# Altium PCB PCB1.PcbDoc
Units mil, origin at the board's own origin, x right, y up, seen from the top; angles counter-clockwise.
Board outline 3605 x 1868.38 mil, 2 copper layers (Top Layer, Bottom Layer); 67 components, 41 nets, 188 pads, 47 vias.
Unrouted connection lines stored in the file: 5.
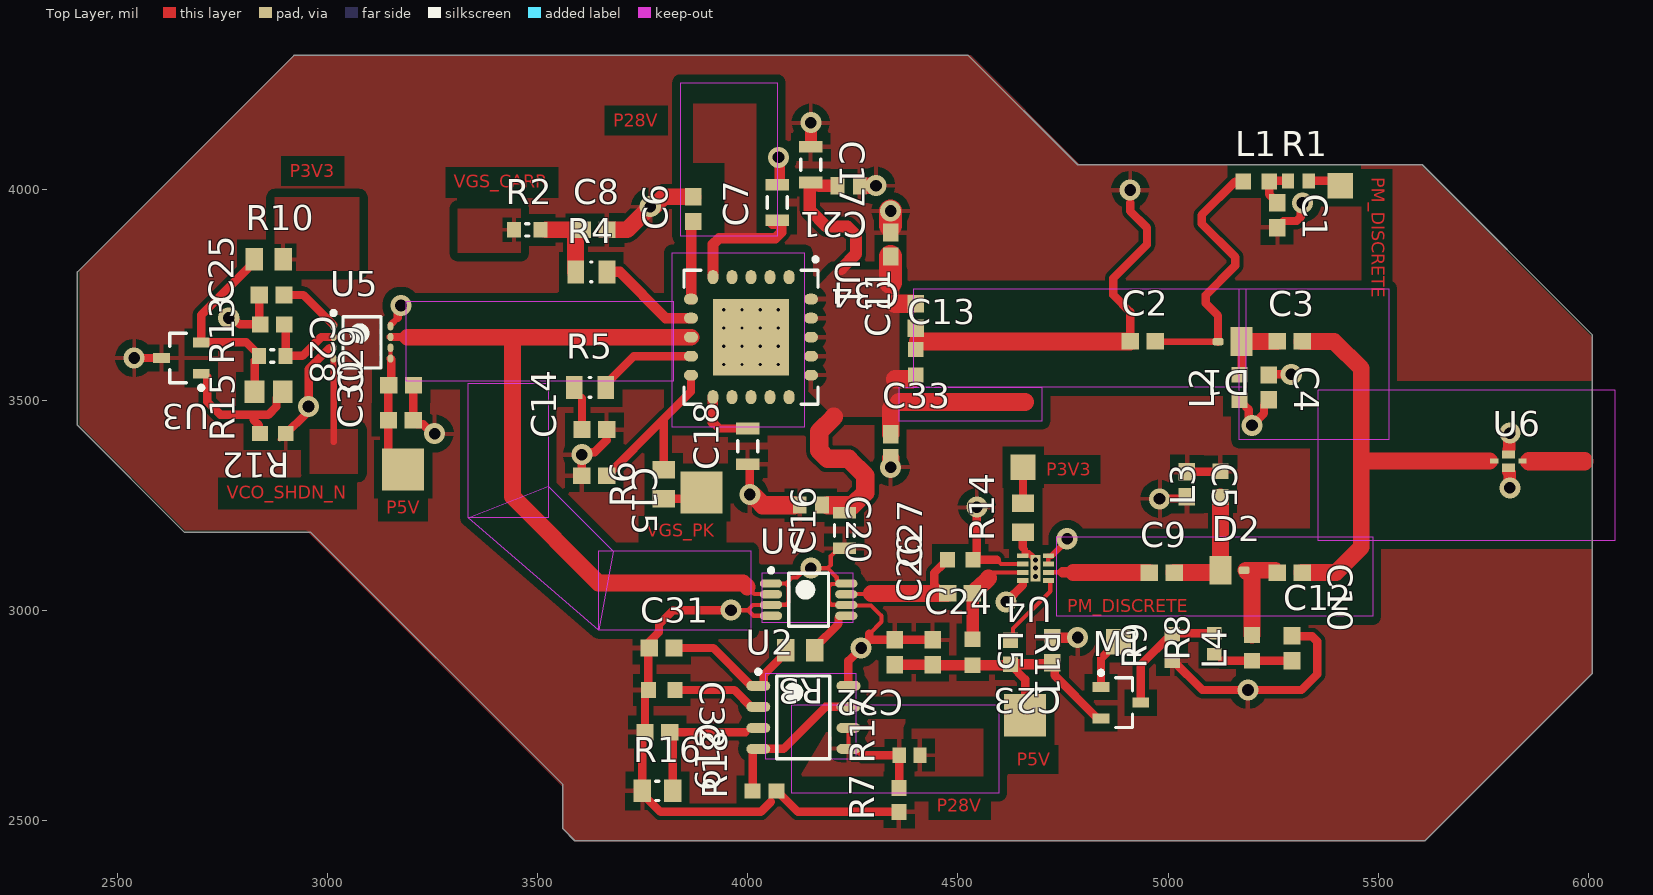
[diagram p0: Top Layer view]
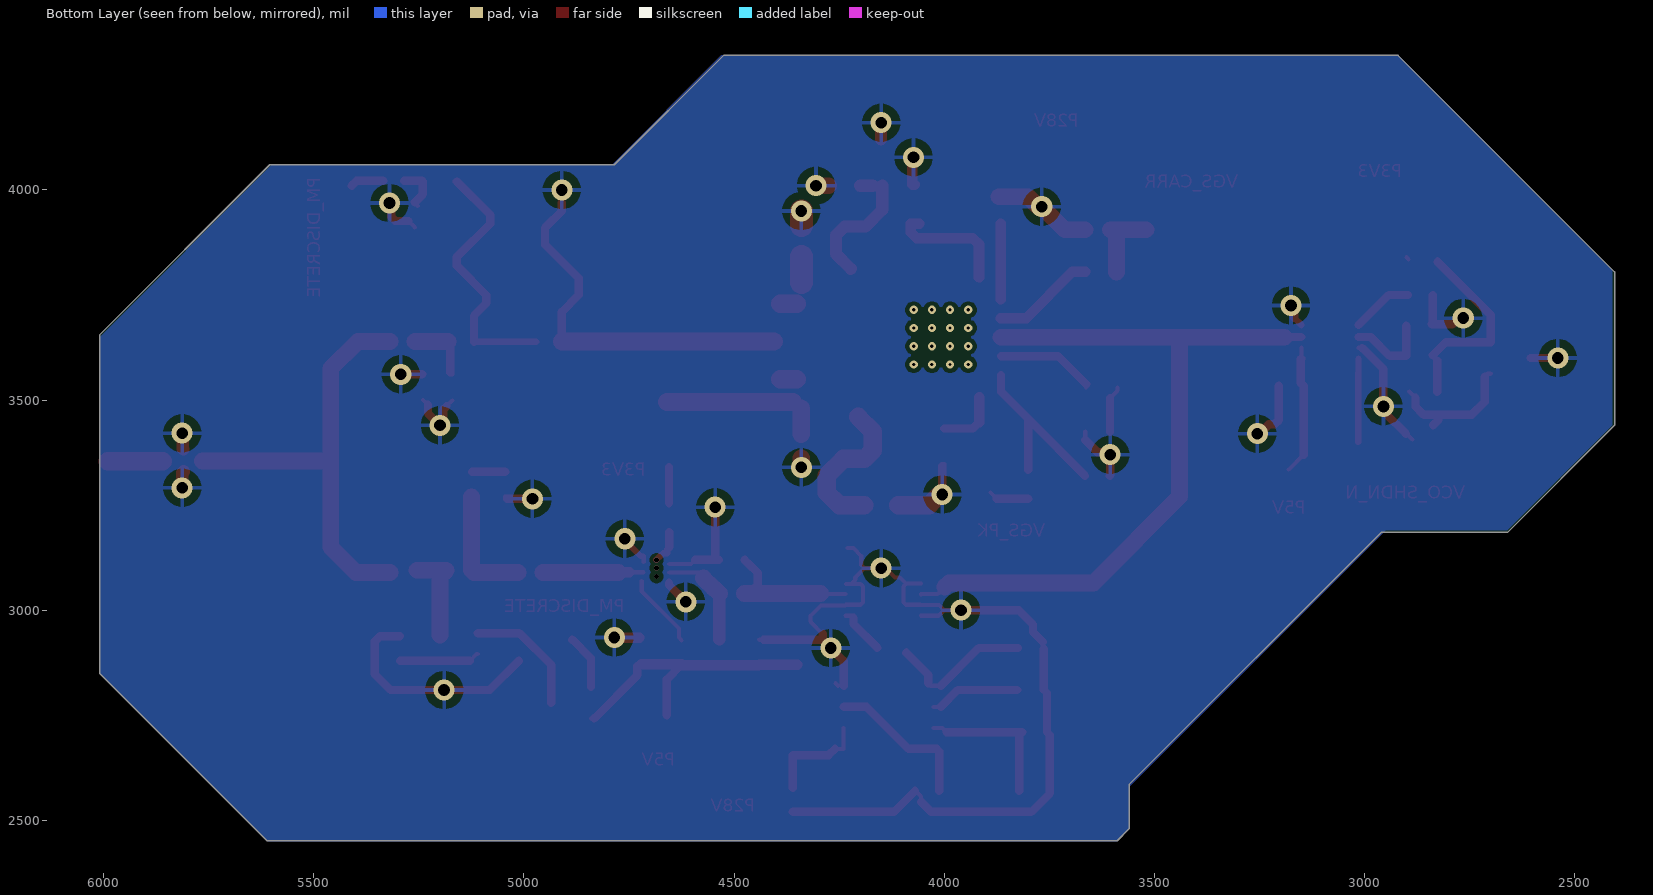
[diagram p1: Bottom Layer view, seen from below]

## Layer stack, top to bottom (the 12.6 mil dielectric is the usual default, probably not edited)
Top Layer: signal copper 1.378
Dielectric 1: dielectric 12.6, FR-4, Dk 4.8
Bottom Layer: signal copper 1.378

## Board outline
2660,3185 2405,3440 2405,3805 2920,4320 4525,4320 4785,4060 5605,4060 6010,3655 6010,2850 5611.62,2451.62 3588.38,2451.62 3560,2480 3560,2585 2960,3185

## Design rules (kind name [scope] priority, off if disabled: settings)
Clearance Clearance_1 [All] p1: gap=10 ignorepadtopadclearanceinfootprint=FALSE except(0: Arc-Hole Track-Hole SMDPad-Hole THPad-Hole Via-Hole Fill-Hole Poly-Hole Region-Hole Text-Hole; 20: Track-Region SMDPad-Poly Fill-Fill Fill-Poly Fill-Region Poly-Poly Poly-Region Region-Region)
PlaneConnect [All] p1: planeconnectstyle=Relief reliefexpansion=20 reliefentries=4 reliefconductorwidth=10 reliefairgap=20
PolygonConnect [All] p1: connectstyle=Relief reliefconductorwidth=10 reliefentries=4 polygonreliefangle="90 Angle" airgapwidth=20
RoomDefinition 33-1-001_R01 [InComponentClass('33-1-001_R01')] p1: confinementstyle=ConfineIn formatcopy=TRUE lockcomponents=FALSE outline 8825,45 14100,45 14100,2135 8825,2135
RoutingVias [All] p1: holewidth=28 width=50 viastyle="Through Hole" minholewidth=28 minwidth=50 maxholewidth=28 maxwidth=50
SolderMaskExpansion [All] p1: expansion=4 istentingtop=FALSE
Width [All] p1: maxlimit=10 minlimit=10 preferedwidth=10
29 further rules are at their usual default settings.

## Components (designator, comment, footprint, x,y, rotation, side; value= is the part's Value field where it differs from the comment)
C1 "C00000013" C0603C101J5GAC7082 5260,3940 r270 top
C2 "C00000013" C0603C101J5GAC7082 4940,3640 r0 top
C3 "C00000013" C0603C101J5GAC7082 5289.53,3639.53 r0 top
C4 "C00000013" C0603C101J5GAC7082 5240,3530 r270 top
C5 "C00000013" C0603C101J5GAC7082 5045,3299.53 r270 top
C6 "C00000007" 06033D105KAT2A 3870,3954.53 r90 top
C7 "C00000003" C2012X5R1V106K125AC 4070,3970 r90 top
C8 "C00000007" 06033D105KAT2A 3635.47,3905 r0 top
C9 "C00000013" C0603C101J5GAC7082 4985,3089.53 r0 top
C10 "C00000013" C0603C101J5GAC7082 5289.53,3089.53 r0 top
C11 "C00000007" 06033D105KAT2A 4400,3700 r90 top
C12 "C00000013" C0603C101J5GAC7082 5295,2909.25 r90 top
C13 "C00000005" CBR06C508A5GAC 4400,3590 r90 top
C14 "C00000007" 06033D105KAT2A 3635,3430 r180 top
C15 "C00000007" 06033D105KAT2A 3634.53,3320 r0 top
C16 "C00000003" C2012X5R1V106K125AC 4230,3190 r90 top
C17 "C00000003" C2012X5R1V106K125AC 4150,4060 r270 top
C18 "C00000003" C2012X5R1V106K125AC 4000,3390 r90 top
C19 "C00000011" C0603C104K4RACTU 3785,2710 r0 top
C20 "C00000004" 06035U9R1BAT2A 4150,3250 r0 top
C21 "C00000004" 06035U9R1BAT2A 4240,4010 r180 top
C22 "C00000007" 06033D105KAT2A 4350,2900 r270 top
C23 "C00000013" C0603C101J5GAC7082 4725,2904.53 r270 top
C24 "C00000013" C0603C101J5GAC7082 4440,2900 r90 top
C25 "C00000011" C0603C104K4RACTU 2866.89,3750 r180 top
C26 "C00000008" GQM1875C2E1R6BB12D 4505,3040 r180 top
C27 "C00000005" CBR06C508A5GAC 4505.51,3120 r180 top
C28 "C00000001" C0603C184J3RACTU 2868.86,3680 r0 top
C29 "C00000012" C0603C221J3RACAUTO 3175,3535 r180 top
C30 "C00000012" C0603C221J3RACAUTO 3174.53,3451.97 r180 top
C31 "C00000007" 06033D105KAT2A 3795,2910 r0 top
C32 "C00000014" AC0603KRX7R8BB103 3795,2810 r0 top
C33 "C00000010" VJ0603D1R8BXCQJHT 4340,3390 r90 top
C34 "C00000010" VJ0603D1R8BXCQJHT 4340,3870 r270 top
D1 "D00000001" SMP1334-084LF 5140,3640 r180 top
D2 "D00000001" SMP1334-084LF 5160,3094 r0 top
L1 "L00000001" ILC0603ER22NJ 5210,4020 r0 top
L2 "L00000001" ILC0603ER22NJ 5170,3530 r90 top
L3 "L00000001" ILC0603ER22NJ 5125,3300 r90 top
L4 "L00000001" ILC0603ER22NJ 5200,2910.24 r90 top
L5 "L00000001" ILC0603ER22NJ 4535,2900 r270 top
M1 "BSS84" BSS84,215 4887.76,2780 r0 top
R1 "R00000009" CR0603-JW-820ELF 5310,4021.57 r0 top
R2 "R00000008" ERJ-U3RD8200V 3475,3905 r0 top
R3 "R00000003" SFR10EZPF10R0 4125,2905 r180 top
R4 "R00000004" CRCW08055R10FKTA 3627.6,3805 r0 top
R5 "R00000004" CRCW08055R10FKTA 3625,3530 r0 top
R6 "R00000003" SFR10EZPF10R0 3800,3300 r90 top
R7 "R00000011" ESR03EZPJ432 4360,2548.54 r90 top
R8 "R00000009" CR0603-JW-820ELF 5110,2920.08 r90 top
R9 "R00000001" ERJ-UP3F8660V 5010,2911.22 r90 top
R10 "R00000005" CR0805-FX-1580ELF 2860.55,3835 r0 top
R11 "R00000011" ESR03EZPJ432 4625,2900 r270 top
R12 "R00000006" ERA-6AEB101V 2860,3520 r180 top
R13 "R00000001" ERJ-UP3F8660V 2868.86,3605 r180 top
R14 "R00000010" CR0805-JW-203ELF 4655,3220 r90 top
R15 "R00000007" "RN73H1JTTD43R7B25 - duplicate" 2870,3420 r180 top
R16 "R00000012" RK73H2ATTD3832F 3785,2570 r0 top
R17 "R00000013" RCS0603499RFKEA 4385,2655 r180 top
R18 "R00000011" ESR03EZPJ432 4040,2570 r180 top
U1 "IC BLM9D2327-26B" BLM9D2327-26B 4007.72,3649.72 r270 top
U2 "IC LM2907" LM2907 4132.28,2745 r0 top
U3 "IC TL4051AQDBZR" TL4051AQDBZR 2652.24,3600 r180 top
U4 "IC QPL9503" QPL9503 4711.57,3117.72 r180 top
U5 "IC MAX 2750 VCO" MAX2750EUA+ 3082.09,3637.2 r0 top
U6 "DEA162495BT-1289A1" DEA162495BT-1289A1 5810,3355 r0 top
U7 "IC HMC213BMS8E" HMC213BMS8E 4145,3025 r0 top

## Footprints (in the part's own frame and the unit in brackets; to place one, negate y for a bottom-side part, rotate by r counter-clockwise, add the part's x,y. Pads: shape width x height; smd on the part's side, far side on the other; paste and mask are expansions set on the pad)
06033D105KAT2A [mm] "Multilayer Ceramic Capacitors MLCC - SMD/SMT 25V 1uF X5R 0603 10%"
  rect 1.05x1 smd: 1(-0.75,0) 2(0.75,0)
  body extent -0.88,-0.48 0.87,0.48, height 0.8
06035U9R1BAT2A [mm] "Multilayer Ceramic Capacitors MLCC - SMD/SMT 50V 9.1pF C0G 0603 0.1pF"
  rect 0.84x1.04 smd: 1(-0.67,0) 2(0.67,0)
  body extent -0.89,-0.51 0.88,0.5, height 0.91
AC0603KRX7R8BB103 [mm] "Multilayer Ceramic Capacitors MLCC - SMD/SMT 25V 0.01uF X7R 0603 10% AEC-Q200"
  rect 0.9x0.95 smd: 1(-0.8,0) 2(0.8,0)
  body extent -0.85,-0.45 0.85,0.45, height 0.55
BLM9D2327-26B [mm] "LDMOS 2-stage integrated Doherty MMIC"
  oval 0.85x0.65 smd: 1(-3.625,2.3) 2(-3.625,1.15) 3(-3.625,0) 4(-3.625,-1.15) 5(-3.625,-2.3) 11(3.625,-2.3) 12(3.625,-1.15) 13(3.625,0) 14(3.625,1.15) 15(3.625,2.3)
  oval 0.65x0.85 smd: 6(-2.3,-3.625) 7(-1.15,-3.625) 8(0,-3.625) 9(1.15,-3.625) 10(2.3,-3.625) 16(2.3,3.625) 17(1.15,3.625) 18(0,3.625) 19(-1.15,3.625) 20(-2.3,3.625)
  rect 4.62x4.62 smd: 21(0,0)
  silkscreen extent -4.82,-4.05 4.05,4.05, body extent -4.05,-4.05 4.05,4.05, height 2.2
BSS84,215 [mm] "MOSFET P-CH DMOS 50V 130MA"
  rect 1x0.6 smd: 1(-1.2,0.95) 2(-1.2,-0.95) 3(1.2,0)
  silkscreen extent -1.32,-1.5 0.7,1.92, body extent -0.7,-1.5 0.7,1.5, height 1.1
C0603C101J5GAC7082 [mm] "MLCC - SMD/SMT 50V 100pF 0603 C0G 0.05"
  rect 1.05x1 smd: 1(-0.75,0) 2(0.75,0)
  body extent -0.88,-0.48 0.87,0.47, height 0.8
C0603C104K4RACTU [mm] "MLCC - SMD/SMT 16V 0.1uF X7R 0603 10%"
  rect 1.05x1 smd: 1(-0.75,0) 2(0.75,0)
  body extent -0.88,-0.48 0.87,0.47, height 0.8
C0603C184J3RACTU [mm] "Multilayer Ceramic Capacitors MLCC - SMD/SMT 25V 0.18uF X7R 0603 5%"
  rect 1x0.95 smd: 1(-0.725,0) 2(0.725,0)
  body extent -0.87,-0.48 0.87,0.48, height 0.8
C0603C221J3RACAUTO [mm] "MLCC - SMD/SMT 25V 220pF X7R 0603 5% AEC-Q200"
  rect 1.05x1 smd: 1(-0.75,0) 2(0.75,0)
  body extent -0.88,-0.48 0.87,0.47, height 0.8
C2012X5R1V106K125AC [mm] "Multilayer Ceramic Capacitors MLCC - SMD/SMT 0805 35V 10uF X5R 10% T: 1.25mm"
  rect 0.7x1.4 smd: 1(-1.075,0) 2(1.075,0)
  silkscreen extent -0.35,-0.6 0.35,0.6, body extent -1,-0.63 1,0.63, height 1.25
CBR06C508A5GAC [mm] "Multilayer Ceramic Capacitors MLCC - SMD/SMT 50V 0.5pF C0G 0603 0.05pF"
  rect 0.9x0.95 smd: 1(-0.775,0) 2(0.775,0)
  body extent -0.85,-0.45 0.85,0.45, height 0.87
CR0603-JW-820ELF [mm] "Thick Film Resistors - SMD 82 OHM 5%"
  rect 0.75x0.9 smd: 1(-0.625,0) 2(0.625,0)
  body extent -0.8,-0.45 0.8,0.45, height 0.8
CR0805-FX-1580ELF [mm] "Thick Film Resistors - SMD 158ohm 1%"
  rect 1.05x1.35 smd: 1(-0.875,0) 2(0.875,0)
  body extent -1.05,-0.67 1.05,0.67, height 0.6
CR0805-JW-203ELF [mm] "Thick Film Resistors - SMD 20K 5%"
  rect 1.05x1.35 smd: 1(-0.875,0) 2(0.875,0)
  body extent -1.05,-0.67 1.05,0.67, height 0.6
CRCW08055R10FKTA [mm] "Thick Film Resistors - SMD 1/8watt 5.1ohms 1%"
  rect 1x1.4 smd: 1(-0.95,0) 2(0.95,0)
  silkscreen extent -0.05,-0.6 0.05,0.6, body extent -1.1,-0.7 1.1,0.7, height 0.5
DEA162495BT-1289A1 [mm] "Multilayer Band Pass Filter  For 2300-2690MHz"
  rect 0.5x0.3 smd: 1(0.85,0) 3(-0.85,0)
  rect 0.8x0.5 smd: 2(0,-0.4) 4(0,0.4)
ERA-6AEB101V [mm] "Thin Film Resistors - SMD 0805 1/8W 100ohms"
  rect 1.2x1.35 smd: 1(-0.85,0) 2(0.85,0)
  body extent -1.1,-0.67 1.1,0.67, height 0.6
ERJ-U3RD8200V [mm] "Thick Film Resistors - SMD 0603 Anti-sulfur"
  rect 0.85x0.95 smd: 1(-0.8,0) 2(0.8,0)
  silkscreen extent -0.1,-0.38 0.1,0.38, body extent -0.88,-0.48 0.87,0.48, height 0.55
ERJ-UP3F8660V [mm] "Thick Film Resistors - SMD 0603 0.25W 1% 866ohm AEC-Q200"
  rect 0.85x0.95 smd: 1(-0.8,0) 2(0.8,0)
  silkscreen extent -0.1,-0.38 0.1,0.38, body extent -0.88,-0.48 0.87,0.48, height 0.55
ESR03EZPJ432 [mm] "Thick FilmResistors - SMD 0603 4.3Kohm 5% Anti Surge AEC-Q200"
  rect 0.95x0.9 smd: 1(-0.725,0) 2(0.725,0)
  body extent -0.85,-0.45 0.85,0.45, height 0.55
GQM1875C2E1R6BB12D [mm] "Multilayer Ceramic Capacitors MLCC - SMD/SMT 0603 1.6pF 250volts C0G 0.1pF"
  rect 1.05x1 smd: 1(-0.75,0) 2(0.75,0)
  body extent -0.88,-0.48 0.87,0.47, height 0.8
HMC213BMS8E [mm] "1.5 GHz to 4.5 GHz, GaAs, MMIC,  Double Balanced Mixer"
  oval 1.35x0.5 smd: 1(-2.275,0.975) 2(-2.275,0.325) 3(-2.275,-0.325) 4(-2.275,-0.975) 5(2.275,-0.975) 6(2.275,-0.325) 7(2.275,0.325) 8(2.275,0.975)
  silkscreen extent -2.4,-1.6 1.2,1.9, body extent -1.6,-1.6 1.6,1.6, height 1.1
ILC0603ER22NJ [mm] "Fixed Inductors 22nH 5%"
  rect 0.94x0.98 smd: 1(-0.78,0) 2(0.78,0)
  body extent -0.88,-0.48 0.87,0.47, height 0.8
LM2907 [mm] "Frequency to Voltage Converter"
  oval 1.45x0.6 smd: 1(-2.725,1.905) 2(-2.725,0.635) 3(-2.725,-0.635) 4(-2.725,-1.905) 5(2.725,-1.905) 6(2.725,-0.635) 7(2.725,0.635) 8(2.725,1.905)
  silkscreen extent -2.85,-2.5 1.6,2.88, body extent -2,-2.5 2,2.5, height 1.75
MAX2750EUA+ [mm] "VCO Oscillators 2.4Ghz Monolithic Voltage-Controlled Oscillators"
  oval 0.35x0.5 smd: 1(-1.725,0.975) 2(-1.725,0.325) 3(-1.725,-0.325) 4(-1.725,-0.975) 5(1.725,-0.975) 6(1.725,-0.325) 7(1.725,0.325) 8(1.725,0.975)
  silkscreen extent -1.85,-1.55 1.15,1.9, body extent -1.55,-1.55 1.55,1.55, height 1.1
QPL9503 [mm] "Ultra Low-Noise, Flat Gain LNA"
  rect 0.674x0.3 smd: 1(-0.1,1.2) 2(-0.1,0.7) 3(-0.1,0.2) 4(-0.1,-0.3) 5(1.45,-0.3) 6(1.45,0.2) 7(1.45,0.7) 8(1.45,1.2)
  rect 0.6x1.6 smd: 5(0.675,0.45)
RCS0603499RFKEA [mm] "Thick Film Resistors - SMD 0.25watt 499ohms 1% 100ppm"
  rect 0.8x0.95 smd: 1(-0.625,0) 2(0.625,0)
  body extent -0.82,-0.48 0.82,0.48, height 0.5
RK73H2ATTD3832F [mm] "Thick Film Resistors - SMD 1/4W 38.3K OHM 1%"
  rect 1.05x1.35 smd: 1(-0.925,0) 2(0.925,0)
  silkscreen extent -0.1,-0.58 0.1,0.58, body extent -1.1,-0.67 1.1,0.67, height 0.6
"RN73H1JTTD43R7B25 - duplicate" [mm] "Chip Resistor, 2-Leads, Body 1.60x0.80mm, IPC Medium Density"
  rect 0.95x0.9 smd: 1(-0.775,0) 2(0.775,0)
  body extent -0.9,-0.45 0.9,0.45, height 0.55
SFR10EZPF10R0 [mm] "Thick Film Resistors - SMD 10ohm 0805 1%"
  rect 1.05x1.35 smd: 1(-0.875,0) 2(0.875,0)
  body extent -1.05,-0.67 1.05,0.67, height 0.65
SMP1334-084LF [mil] "100 W High-Power Silicon PIN Diode"
  rect 53.15x68.9 smd: 1(-35,1)
  rrect50% 25.59x17.72 smd: 2(21,1)
TL4051AQDBZR [mm] "Voltage References Precision Micropower Shunt Vltg Ref"
  rect 1x0.6 smd: 1(-1.2,0.95) 2(-1.2,-0.95) 3(1.2,0)
  silkscreen extent -1.33,-1.5 0.7,1.92, body extent -0.7,-1.52 0.7,1.52, height 1.1
VJ0603D1R8BXCQJHT [mm] "Multilayer Ceramic Capacitors MLCC - SMD/SMT 1.8pF 200V 0.1% C0G"
  rect 1.1x0.95 smd: 1(-0.725,0) 2(0.725,0)
  body extent -0.87,-0.46 0.87,0.46, height 0.94

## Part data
C1 C2 C3 C4 C5 C9 C10 C12 C23 C24: "MLCC 100pF 5% 50V 0603", Capacitance=100pF, Dielectric=C0G, Package=0603, Tolerance=5%, Voltage=50V
C6 C8 C11 C14 C15 C22 C31: "MLCC 1uF 25V X5R 0603", Capacitance=1uF, Dielectric=X5R, Package=0603, Tolerance=10%, Voltage=25V
C7 C16 C17 C18: "MLCC 10uF 35V X5R 0805", Capacitance=10uF, Dielectric=X5R, Package=0805, Tolerance=20%, Voltage=35V
C13 C27: "MLCC 0.5pF 50V 0603 C0G", Capacitance=0.5pF, Dielectric=C0G, Package=0603, Tolerance=0.05pF, Voltage=50V
C19 C25: "MLCC 0.1uF 16V 0603 X7R", Capacitance=0.1uF, Dielectric=X7R, Package=0603, Tolerance=10%, Voltage=16V
C20 C21: "MLCC 9.1pF 50V 0603 C0G", Capacitance=9.1pF, Dielectric=C0G, Package=0603, Tolerance=0.1pF, Voltage=50V
C26: "MLCC 5.6pF 250V C0G 0603", Capacitance=5.6pF, Dielectric=C0G, Package=0603, Tolerance=20%, Voltage=250V
C28: "MLCC 180nF 25V X7R 0603", Capacitance=180nF, Dielectric=X7R, Package=0603, Tolerance=5%, Voltage=25V
C29 C30: "MLCC 220pF 5% 25V 0603 X7R", Capacitance=220pF, Dielectric=X7R, Package=0603, Tolerance=5%, Voltage=25V
C32: "MLCC 10nF 25V 10% 0603 X7R", Capacitance=10nF, Dielectric=X7R, Package=0603, Tolerance=10%, Voltage=25V
C33 C34: "MLCC 1.8 pF 250V C0G 0603", Capacitance=1.8pF, Dielectric=C0G, Package=0603, Tolerance=0.1pF, Voltage=200V
D1 D2: "PIN DIODE .45 Pf .45 OHM .37 nH, 1-8GHz, SMP1334-084LF"
L1 L2 L3 L4 L5: "22nH 300mA 0603 RF Inductor", Inductance=22nH, Package=0603
M1: "MOSFET P-CH DMOS 50V 130MA"
R1 R8: "RES CHIP 82E 5% 1/10W", Package=0603, Power=1/10W, Resistance=82E, Tolerance=1%, Voltage Rating=50V
R2: "RES CHIP 820E 1%", Package=0603, Power=1/4W, Resistance=820E, Tolerance=1%, Voltage Rating=150
R3 R6: "RES CHIP 10E 0805 1%", Package=0805, Resistance=10E, Tolerance=1%
R4 R5: "RES CHIP 5.1E 0805 1%", Package=0805, Power=1/8W, Resistance=5.1E, Tolerance=1%, Voltage Rating=150V
R7 R11 R18: "RES CHIP 4.3k 5% 0603 ESR03EZPJ432", Package=0603, Power=1/4W, Resistance=4.3k, Tolerance=5%, Voltage Rating=150V
R9 R13: "RES CHIP 866 0603 1%", Package=0603, Power=1/4W, Resistance=866E, Tolerance=1%, Voltage Rating=150V
R10: "RES CHIP 158E 0805 1%", Package=0805, Power=1/8W, Resistance=158E, Tolerance=1%, Voltage Rating=150V
R12: "RES CHIP 100E 0.1%", Package=0805, Power=1/8W, Resistance=100E, Tolerance=0.1%, Voltage Rating=100V
R14: "RES CHIP 20k 5% / CR0805-JW-203ELF", Package=0805, Power=1/8W, Resistance=20k, Tolerance=5%, Voltage Rating=150V
R15: "RES CHIP 43.7E 0603 0.1%", Package=0603, Power=1/10W, Resistance=43.7E, Tolerance=0.1%, Voltage Rating=75V
R16: "RES CHIP 38.3k 1% 0805", Package=0805, Power=1/4W, Resistance=38.3k, Tolerance=1%, Voltage Rating=150V
R17: "RES CHIP 499E 1% 0603 75V", Package=0603, Power=1/4W, Resistance=499E, Tolerance=1%, Voltage Rating=75V
U1: "LDMOS 2-stage integrated Doherty MMIC"
U3: "Precision voltage reference"
U5: "2.4-2.5 GHz VCO"
U6: "2.5GHz BPF"

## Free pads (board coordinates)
  rect 60x60 smd: 1(4882.5,2925) 1(5410.08,4010) 4(4655,3340)
  rect 100x100 smd: 3(3180,3335) 3(3890,3280) 3(4660,2750)

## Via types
v1: diameter 50, hole 28, Top Layer to Bottom Layer, 28 vias
v2: diameter 19.68, hole 7.87, Top Layer to Bottom Layer, 16 vias
v3: diameter 11.81, hole 11.81, Top Layer to Bottom Layer, 3 vias

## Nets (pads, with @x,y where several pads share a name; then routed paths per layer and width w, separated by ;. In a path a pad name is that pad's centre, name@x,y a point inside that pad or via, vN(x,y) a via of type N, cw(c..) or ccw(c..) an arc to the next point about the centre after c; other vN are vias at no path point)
GND: C1.2 C4.1 C4.2 C5.1 C5.2 C6.2 C7.2 C8.2 C12.2 C14.1 C15.1 C16.1 C17.1 C18.1 C19.1 C20.1 C21.1 C22.1 C23.1 C24.2 C25.2 C27.1 C28.1 C29.1 C30.1 C31.1 C32.1 C33.1 C34.1 L2.1 L3.2 R7.1 R9.1 R15.1 R16.1 R18.1 U2.8 U3.3 U4.3 U4.4 U4.6 U4.8 U5.3 U5.8 U6.2 U6.4 U7.1 U7.3 U7.4 U7.6 U7.8 | length 5379.6
  Top Layer w10: v1(2765,3695) v1@2775.82,3695 ; C25.2@2835.47,3750 C25.2@2837.44,3751.97 ; C28.1@2837.36,3682.95 C28.1 ; R15.1@2886.46,3405.95 R15.1 R15.1@2901.5,3420 ; v1@2947.35,3465.85 2947.35,3477.35 v1(2955,3485) ; 3005.11,3623.66 3013.43,3623.66 U5.3 ; U5.8 U5.8@3150,3678.54 ; v1@3167.35,3717.35 v1(3175,3725) ; v1@3250,3420 v1(3255,3420) ; C15.1@3604.02,3320 C15.1 ; 3664.53,3404.53 C14.1@3664.53,3425 ; R16.1@3748.58,2564.09 R16.1 ; C19.1@3748.58,2703.11 C19.1 ; C32.1@3755.47,2801.97 C32.1 ; C31.1 C31.1@3765.47,2924.53 ; v1(3767.97,3960.03) v1@3776.5,3960.03 ; v1(3960,3000) 4000.59,3000 ; C18.1 C18.1@4004.82,3342.85 ; v1(4004.82,3275.18) v1@4007.93,3275.18 ; v1@4004.82,3278.28 v1@4007.93,3275.18 ; v1@4011.04,3275.18 v1@4007.93,3275.18 ; 4055,2544.13 4055,2557.28 4067.72,2570 R18.1 R18.1@4069.53,2570 ; U7.4 4055.32,2986.73 4013.86,2986.73 4000.59,3000 ; U7.1 4091.15,3063.39 4105.63,3077.87 4117.04,3077.87 4139.18,3100 v1(4150,3100) 4189.77,3100 ; 4091.15,3062.64 4097.01,3056.78 4097.01,3018.81 4091.15,3012.95 4056.18,3012.95 U7.3 4012.79,3012.2 4000.59,3000 ; C16.1 4216.22,3147.68 4197.65,3129.11 4197.65,3107.65 4190,3100 4189.77,3100 ; U7.8@4233.82,3062.64 U7.8@4221.2,3062.64 ; U2.8@4252.61,2820 U2.8@4258.91,2826.29 ; v1(4270,2910) 4289.53,2929.53 ; 4289.53,2943.67 4318.36,2972.5 4318.36,2986.64 4293.54,3011.46 4235.31,3011.46 4233.82,3012.95 4198.85,3012.95 4192.99,3018.81 4192.99,3056.78 4198.85,3062.64 U7.8@4221.2,3062.64 ; C22.1 C22.1@4350.47,2930 ; C24.2@4430,2930 4430.47,2929.53 C24.2 ; C27.1 C27.1@4545,3128.98 ; 4592.4,3120 4602.56,3109.84 U4.6 ; U4.3@4715,3114.92 4715,3129.02 U4.4 U4.4@4722.87,3129.53 ; C23.1 C23.1@4725.94,2935 ; v1@4760,3166.65 v1(4760,3170) ; R9.1@5008.03,2879.72 R9.1 R9.1@5011.97,2879.72 ; C5.2@5040,3265 C5.2 ; C5.1 C5.1@5046.65,3330.71 ; L3.2@5123.35,3329.06 L3.2 ; L2.1 5170.79,3499.29 5184.29,3485.79 L2.1@5184.29,3485 ; v1@5192.35,3447.65 v1(5200,3440) ; C4.2@5228.28,3488.76 C4.2 ; C4.1 C4.1@5241.76,3561.29 ; C1.2 5260,3911.46 C1.2@5274.69,3926.14 ; C12.2@5295,2937.8 C12.2 ; v1@5316.14,3965 v1(5320,3968.86) ; U6.2@5810,3330 U6.2 ; 4189.77,3100 4211.62,3078.16 4211.62,3072.23 U7.8@4221.2,3062.64
  Top Layer w15: U5.8@3150,3678.54 3167.35,3695.89 ; U4.4@4722.87,3129.53 v1@4760,3166.65
  Top Layer w20: v1(2540,3600) U3.3 ; v1@2775.82,3695 2790.82,3680 C28.1 ; C28.1@2837.36,3682.95 C25.2 ; R15.1@2901.5,3420 v1@2947.35,3465.85 ; v1(2955,3485) 2955,3573.56 3005.11,3623.66 ; 3167.35,3695.89 v1@3167.35,3717.35 ; C29.1@3204.06,3534.53 C30.1 3213.74,3442.28 3227.72,3442.28 v1@3250,3420 ; C15.1@3606.2,3320.21 3605,3321.41 v1(3605,3370) 3610.74,3375.74 3635.74,3375.74 3664.53,3404.53 ; R16.1@3748.58,2564.09 3792.68,2520 4030.87,2520 4055,2544.13 ; R16.1 C19.1@3748.58,2703.11 ; C19.1 C32.1@3755.47,2801.97 ; C32.1 C31.1@3763.5,2908.03 ; C31.1@3765.47,2924.53 3788.86,2947.91 3788.86,2965.9 3822.96,3000 v1(3960,3000) ; v1@4004.82,3278.28 C18.1@4004.82,3342.85 ; R18.1@4069.53,2570 4119.53,2520 R7.1 ; U2.8 4239.57,2879.57 v1(4270,2910) ; 4289.53,2943.67 4289.53,2929.53 C22.1 ; C22.1@4350.47,2930 C24.2@4430,2930 ; C27.1 4592.4,3120 ; C27.1@4545,3128.98 v1(4545,3245) ; v1(4615,3020) 4655,3060 U4.8@4655,3065 ; v1(4980,3265) C5.2@5040,3265 ; R9.1@5011.97,2879.72 5081.69,2810 v1(5190,2810) 5317.54,2810 5354.82,2847.28 5354.82,2926.08 5343.1,2937.8 C12.2@5295,2937.8 ; C5.1 L3.2@5123.35,3329.06 ; L2.1@5184.29,3485 5192.35,3476.94 v1@5192.35,3447.65 ; v1(5200,3440) 5228.28,3468.28 C4.2@5228.28,3488.76 ; C4.1@5241.76,3561.29 v1(5293.23,3561.29) ; C1.2@5274.69,3926.14 5306.14,3926.14 5316.14,3936.14 v1@5316.14,3965
  Top Layer w25: C7.2 4075.32,4012.32 4076.6,4013.6 4076.6,4074.08 v1(4072.97,4077.71) ; C23.1@4725.94,2935 v1(4785,2935)
  Top Layer w28.7: 4150,4120 v1(4150,4160)
  Top Layer w30: U6.2@5810,3330 5813.23,3326.77 v1(5813.23,3291.29) ; 5810.75,3383.17 5811.56,3383.97 5811.56,3419.61 v1(5813.23,3421.29)
  Top Layer w39.87: C8.2 3712.94,3905 v1(3767.97,3960.03) ; v1@3776.5,3960.03 3800.52,3984.06 C6.2
  Top Layer w40: C21.1@4275.6,4010 v1@4294.52,4010
  Top Layer w42: v1(4340,3340) C33.1
  Top Layer w44: v1@4011.04,3275.18 4036.21,3250 C20.1@4110,3250
  Top Layer w55: C34.1@4340,3915 v1(4340,3950)
  other v1: 4910,4000 4305,4010
NetC1_1: C1.1 L1.2 R1.1 | length 114.3
  Top Layer w10: L1.2 L1.2@5242.28,4021.57 ; C1.1@5252.59,3962.12 C1.1 C1.1@5260,3970.51
  Top Layer w20: L1.2 5240.71,3989.8 C1.1@5260,3970.51 ; L1.2@5242.28,4021.57 R1.1
NetC2_1: C2.1 C11.1 C13.2 | length 901.7
  Top Layer w20: C2.1@4910,3639.53 4910,3710 4870,3750 4870,3790 4950,3870 4950,3910 4910,3950 4910,3970
  Top Layer w43: 4405,3639.53 C2.1@4910,3639.53
NetC2_2: C2.2 D1.2 L1.1 | length 638.2
  Top Layer w10: C2.2 C2.2@4970.53,3639
  Top Layer w16: C2.2@4970.53,3639 D1.2
  Top Layer w20: D1.2 5119,3701 5090,3730 5090,3750 5160,3820 5160,3840 5080,3920 5080,3940 5160,4020
NetC3_1: C3.1 D1.1 L2.2 | length 160.4
  Top Layer w10: L2.2 L2.2@5175,3565.71
  Top Layer w20: L2.2@5175,3565.71 D1.1
  Top Layer w39.87: D1.1@5180,3639.53 C3.1
NetC3_2: C3.2 C10.2 U6.3 | length 1063.7
  Top Layer w39.87: C10.2 5399.53,3089.53 5460,3150 5460,3355 ; C3.2 5395.47,3639.53 5460,3575 5460,3355 ; 5765.06,3355 5460,3355
NetC6_1: C6.1 U1.6 | length 186.8
  Top Layer w10: C6.1@3865,3920 C6.1
  Top Layer w25: U1.6 C6.1@3865,3920
NetC7_1: C7.1 R17.1 U1.5 | length 287.6
  Top Layer w25: U1.5 3917.28,3792.55 3917.28,3870.36 3931.92,3885 4065.3,3885 4079.94,3899.64 C7.1@4079.94,3919.07 ; C7.1@4059.94,3919.07 4060.87,3920 C7.1@4075,3920
NetC8_1: C8.1 R2.2 R4.1 | length 192.1
  Top Layer w10: C8.1@3590.2,3890.24 3604.96,3905 C8.1
  Top Layer w39.87: R2.2@3520,3905 3590.2,3905 C8.1@3604.96,3905 ; R4.1 C8.1@3590.2,3890.24
NetC9_1: C9.1 U4.2 | length 220
  Top Layer w10: U4.2 4749.84,3090.16 4750,3090
  Top Layer w25: 4750,3090 4755,3090
  Top Layer w39.87: 4775,3089.53 C9.1
NetC9_2: C9.2 D2.1 L3.1 | length 287
  Top Layer w10: D2.1@5119.53,3089.53 D2.1
  Top Layer w39.87: C9.2 D2.1@5119.53,3089.53 ; D2.1 L3.1
NetC10_1: C10.1 D2.2 L4.2 | length 241.6
  Top Layer w10: D2.2 D2.2@5184.94,3095 ; C10.1@5254.53,3095 C10.1
  Top Layer w39.87: L4.2 5200,3079.94 5184.94,3095 C10.1@5254.53,3095
NetC11_2: C11.2 C13.1 C16.2 C17.2 C20.2 C21.2 C33.2 C34.2 U1.16 U1.17 U1.18 U1.19 U1.20 | length 1191.9
  Top Layer w10: 4350,3550 4350.51,3549.49 ; 4350,3730 4350.47,3729.53
  Top Layer w28.7: C17.2@4147.5,4010 4147.5,3952.5 4187.5,3912.5 4237.5,3912.5 4257.5,3892.5 4257.5,3847.5 4222.5,3812.5 ; C17.2@4170,4010 C21.2@4200,4010
  Top Layer w42: C33.2 4340,3480
  Top Layer w43: 4360,3495 4660,3495
  Top Layer w44: C20.2@4190,3250 4250,3250 4280,3280 4280,3320 4240,3360 4190,3360 4170,3380 4170,3425 4205,3460 ; 4350.47,3729.53 C11.2@4390,3729.53 ; 4350.51,3549.49 C13.1@4390,3549.49
  Top Layer w55: 4340,3780 C34.2
NetC12_1: C12.1 L4.1 R8.1 | length 191.7
  Top Layer w10: R8.1 5112.95,2895.47 5128.9,2879.53 ; L4.1 L4.1@5200.2,2879.72
  Top Layer w20: 5128.9,2879.53 L4.1 ; L4.1@5200.2,2879.72 C12.1
NetC14_2: C14.2 R5.1 | length 112.4
  Top Layer w10: R5.1 3587.6,3522.13 R5.1@3605.47,3504.25
  Top Layer w20: C14.2@3605.47,3425 R5.1@3605.47,3504.25
NetC15_2: C15.2 R6.2 U1.10 | length 442
  Top Layer w10: C15.2 C15.2@3665.04,3320 ; 3797.52,3452.48 3800,3450
  Top Layer w20: C15.2@3665.04,3320 3797.52,3452.48 3865,3519.96 U1.10 ; R6.2 3800,3450
NetC18_2: C18.2 U1.11 | length 148.8
  Top Layer w20: 3917.17,3447.25 3932.1,3432.32 C18.2
  Top Layer w25: 3917.17,3447.25 U1.11
NetC19_2: C19.2 R16.2 U2.3 | length 357.5
  Top Layer w10: C19.2 C19.2@3821.42,2703.11 ; 3994.58,2710 4004.58,2720 U2.3
  Top Layer w20: C19.2 3994.58,2710 ; R16.2 C19.2@3821.42,2703.11
NetC22_2: C22.2 C23.2 C24.1 C29.2 C30.2 L5.2 M1.2 pad.3@3180,3335 pad.3@4660,2750 R11.2 U5.5 U5.6 | length 1103.7
  Top Layer w10: pad.3@3145,3370 pad.3@3180,3335 ; U5.5 U5.6 ; C24.1@4441.18,2869.29 C24.1 4539.53,2870.47 L5.2@4540.71,2869.29 ; R11.2 4622.83,2869.29 R11.2@4626.18,2869.29 ; C23.2@4721.46,2871.46 C23.2 ; C23.2@4725,2871.46 C23.2@4730.05,2866.41 ; M1.2@4832.64,2742.6 M1.2
  Top Layer w20: pad.3@3145,3370 C30.2 C29.2@3145,3534.53 ; C29.2 3151.64,3541.17 3151.64,3597.18 U5.5 ; R11.2@4626.18,2869.29 4660,2835.47 pad.3@4660,2750 ; C23.2@4730.05,2866.41 4730.05,2845.19 M1.2@4832.64,2742.6
  Top Layer w25: C22.2 C24.1 ; C24.1@4441.18,2869.29 L5.2 4540.71,2869.29 R11.2@4622.83,2869.29 ; R11.2 C23.2@4721.46,2871.46
NetC25_1: C25.1 U5.1 | length 148.4
  Top Layer w10: U5.1@3014.17,3677.52 U5.1@3014.17,3678.54
  Top Layer w20: C25.1 2942.72,3750 U5.1@3014.17,3678.54
NetC26_1: C26.1 L5.1 U4.7 | length 232.7
  Top Layer w10: 4585.35,3089.84 U4.7@4654.49,3089.84
  Top Layer w30: L5.1 C26.1@4535,3039.53
  Top Layer w39.87: C26.1 4535.01,3040 4547.47,3052.46 4549.54,3052.46 4572.89,3075.82 4572.89,3077.38
NetC26_2: C26.2 C27.2 U7.7 | length 354.2
  Top Layer w10: U7.7@4235,3038.23 4291.77,3038.23 4293.55,3040
  Top Layer w20: C27.2 4475,3119.02 4467.28,3111.3 4466.3,3111.3 4443.52,3088.52 4443.52,3061.4 4455.24,3049.69 4465.79,3049.69 C26.2
  Top Layer w39.87: 4293.55,3040 4443.52,3040 C26.2
NetC28_2: C28.2 R13.1 U5.2 | length 208.7
  Top Layer w10: C28.2 C28.2@2900.35,3677.05
  Top Layer w20: C28.2@2900.35,3677.05 R13.1 2940.13,3605 2985.13,3650 U5.2
NetC31_2: C31.2 R3.2 U2.1 | length 354
  Top Layer w10: U2.1@4008.27,2820 U2.1 4031.98,2820 U2.1@4038.27,2826.29 ; R3.2@4090.55,2899.09 R3.2
  Top Layer w20: C31.2 3918.27,2910 U2.1@4008.27,2820 ; U2.1@4038.27,2826.29 4038.27,2846.81 R3.2@4090.55,2899.09
NetC32_2: C32.2 U2.2 | length 215.1
  Top Layer w10: U2.2@4008.27,2770 U2.2
  Top Layer w20: C32.2 3968.27,2810 U2.2@4008.27,2770
NetM1_1: M1.1 pad.1 R1.2 U5.4 | length 416
  Top Layer w10: pad.1@4882.5,2925 pad.1@4885,2930
  Top Layer w15: U5.4 3014.17,3565.83 3015,3565 3015,3400
  Top Layer w20: M1.1 4840.51,2885.51 pad.1@4885,2930 ; R1.2 5398.5,4021.57 pad.1@5410.08,4010
NetM1_3: M1.3 R8.2 R9.2 | length 295.8
  Top Layer w10: R9.2@5008.03,2942.72 R9.2 R9.2@5011.97,2944.68
  Top Layer w20: M1.3 4935,2869.68 R9.2@5008.03,2942.72 ; R9.2@5011.97,2944.68 R8.2
NetR2_1: R2.1
NetR3_1: R3.1 U7.5 | length 121
  Top Layer w10: R3.1 R3.1@4159.45,2910.91 ; U7.5@4215.98,2982.14 4220.46,2986.61 U7.5
  Top Layer w20: R3.1@4159.45,2910.91 4215.98,2967.44 U7.5@4215.98,2982.14
NetR4_2: R4.2 U1.7 | length 245.6
  Top Layer w25: R4.2 3695,3805 3805,3695 U1.7
NetR5_2: R5.2 U1.9 | length 238
  Top Layer w10: R5.2 R5.2@3662.4,3537.87
  Top Layer w20: R5.2@3662.4,3537.87 3728.98,3604.45 U1.9
NetR6_1: pad.3@3890,3280 R6.1 | length 96
  Top Layer w10: pad.3@3875.55,3265.55 pad.3@3890,3280
  Top Layer w20: R6.1 pad.3@3875.55,3265.55
NetR7_2: R7.2 R17.2 U2.5 U2.6 | length 255.1
  Top Layer w10: U2.6 U2.5 U2.5@4259.99,2670 ; R17.2@4360,2654.61 R17.2
  Top Layer w20: U2.5@4259.99,2670 4274.99,2655 R17.2 ; R7.2 R17.2@4360,2654.61
NetR10_1: R10.1 R12.2 R13.2 U3.2 | length 492
  Top Layer w10: R10.1@2826.1,3829.09 R10.1 ; R13.2@2826.54,3594.17 R13.2 R13.2@2837.36,3606.97
  Top Layer w20: R10.1@2826.1,3829.09 2699.49,3702.48 U3.2 2806.93,3637.4 R13.2@2837.36,3606.97 ; R12.2 R13.2@2826.54,3594.17
NetR10_2: pad.4 R10.2 R14.2 | length 92.6
  Top Layer w10: R10.2 R10.2@2900,3840
  Top Layer w20: R14.2 pad.4
NetR11_1: R11.1 U4.1 | length 180.1
  Top Layer w10: R11.1 4631.39,2934.93 4631.39,2956.39 4720,3045 U4.1@4720,3069.25
NetR12_1: R12.1 R15.2 U3.1 | length 335.5
  Top Layer w10: U3.1 2707.36,3562.6 U3.1@2714.17,3555.79 ; 2836.67,3440 2837.36,3440 ; R12.1@2878.58,3505.12 R12.1
  Top Layer w20: U3.1@2714.17,3555.79 2714.17,3495.83 2745,3465 2823.95,3465 ; 2836.67,3440 2823.95,3452.72 2823.95,3465 ; R12.1@2878.58,3505.12 2878.58,3484.28 2859.3,3465 2823.95,3465
NetR14_1: R14.1 U4.5 | length 84.5
  Top Layer w10: R14.1@4654.49,3185.04 R14.1
  Top Layer w15: 4654.49,3150 4659.3,3145.19 4659.3,3135.56 4668.93,3135.56 4673.74,3130.75 4673.97,3130.75 v3(4685,3119.68)
  Top Layer w20: 4654.49,3150 R14.1@4654.49,3185.04
  other v3: 4685,3080.31 4685,3100
NetR18_2: R18.2 U2.4 U2.7 | length 365.8
  Top Layer w10: U2.4@4011.46,2663.71 U2.4@4017.75,2670
  Top Layer w20: R18.2 U2.4@4011.46,2663.71 ; U2.4@4017.75,2670 4085,2670 4185,2770 U2.7
NetU1_8: U1.8 U5.7 U7.2 | length 1806.5
  Top Layer w10: 3190,3650 3190.28,3649.72 ; 3998.92,3055 4015.38,3038.54 4054.68,3038.54 U7.2
  Top Layer w20: U5.7 3190,3650
  Top Layer w39.87: 3190.28,3649.72 3440,3649.72 ; U1.8 3440,3649.72 ; 3998.92,3055 3988.92,3065 3645,3065 3440,3270 3440,3649.72
NetU6_1: U6.1 | length 130
  Top Layer w44: 5860,3355 5990,3355
pads on no net: U1.1 U1.2 U1.3 U1.4 U1.12 U1.13 U1.14 U1.15 U1.21
copper on no net:
  other v2: 3942.76,3584.76 3986.06,3584.76 4029.37,3584.76 4072.68,3584.76 3942.76,3628.07 3986.06,3628.07 4029.37,3628.07 4072.68,3628.07 3942.76,3671.38 3986.06,3671.38 4029.37,3671.38 4072.68,3671.38 3942.76,3714.68 3986.06,3714.68 4029.37,3714.68 4072.68,3714.68

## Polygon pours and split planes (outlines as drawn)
GND on Top Layer "GND_L01_P015" (solid, pour order 15): 5610,2450 3590,2450 3560,2480 3560,2580 2950,3190 2660,3190 2410,3440 2410,3810 2920,4320 4530,4320 4790,4060 5600,4060 6010,3650 6010,2850
NetC7_1 on Top Layer "NETC7_1_L01_P011" (solid, pour order 11): 4390,2717.5 4560,2717.5 4560,2605 4390,2605
NetR7_2 on Top Layer "NETR7_2_L01_P012" (solid, pour order 12): 4205,2740 4375,2740 4375,2605 4125,2605
NetC11_2 on Top Layer "NETC11_2_L01_P001" (solid, pour order 1): 4205,3810 4360,3810 4360,3460 4205,3460 4140,3525 4140,3745
NetC7_1 on Top Layer "NETC7_1_L01_P009" (solid, pour order 9): 3870,4205 4020,4205 4020,4065 3870,4065
NetC7_1 on Top Layer "NETC7_1_L01_P008" (solid, pour order 8): 3945,4130 4020,4130 4020,3880 3945,3880
NetR2_1 on Top Layer "NETR2_1_L01_P005" (solid, pour order 5): 3460,3955 3460,3850 3310,3850 3310,3955
NetM1_1 on Top Layer "NETM1_1_L01_P004" (solid, pour order 4): 2957.5,3430.02 3072.5,3430.02 3072.5,3325 2957.5,3325
NetR10_2 on Top Layer "NETR10_2_L01_P003" (solid, pour order 3): 2875,3807.5 3075,3807.5 3075,3982.5 2875,3982.5
GND on Bottom Layer "GND_L02_P016" (solid, pour order 16): 5610,2450 3590,2450 3560,2480 3560,2580 2950,3190 2660,3190 2410,3440 2410,3810 2920,4320 4530,4320 4790,4060 5600,4060 6010,3650 6010,2850

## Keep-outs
Top Layer:
  region: 4700,3530 4700,3450 4360,3450 4360,3530
  region: 3840,4255 4070,4255 4070,3890 3840,3890
  region: 4105,2775 4597.5,2775 4597.5,2565 4105,2565
  region: 4257.5,2850 4257.5,2645.55 4042.5,2645.55 4042.5,2850
  region: 4250,3089.45 4250,2970 4035,2970 4035,3089.45
  region: 3680,3140 3645,2951.77 3335,3220 3525,3295
  region: 3645,3141.77 4007.15,3141.77 4007.15,2951.77 3645,2951.77
  region: 5525,3765 5525,3405 5170,3405 5170,3765
  region: 3820,3850 4135,3850 4135,3435 3820,3435
  region: 3187.5,3735 3822.5,3735 3822.5,3545 3187.5,3545
  region: 4735,3175 5487.5,3175 5487.5,2985 4735,2985
  region: 3525,3540 3525,3220 3335,3220 3335,3540
  region: 6062.5,3525 6062.5,3165 5357.5,3165 5357.5,3525
  region: 5185.17,3765 5185.17,3530 4394.83,3530 4394.83,3765

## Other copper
Top Layer:
  text "P28V" at 3680,4150 h30
  text "P3V3" at 2910,4030 h30
  text "PM_DISCRETE" at 5485,4030 h30 r270
  text "VGS_CARR" at 3300,4005 h30
  text "P3V3" at 4710,3320 h30
  text "VCO_SHDN_N" at 2760,3265 h30
  text "P5V" at 3140,3230 h30
  text "VGS_PK" at 3760,3175 h30
  text "PM_DISCRETE" at 4760,2995 h30
  text "P5V" at 4640,2630 h30
  text "P28V" at 4450,2520 h30

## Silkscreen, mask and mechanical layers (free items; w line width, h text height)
Mechanical 1:
  the board outline again, w10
